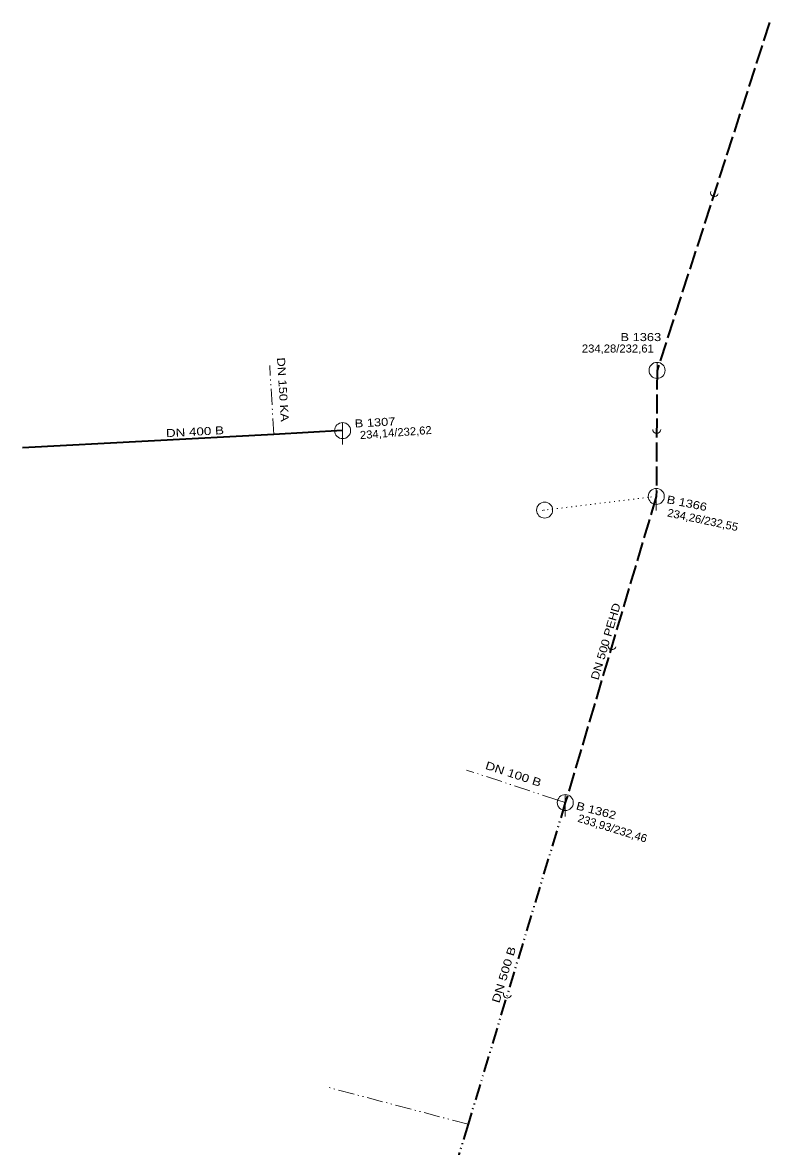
# Model space of a CAD drawing. Extents: x -645297 to -645138, y -1043752 to -1043474.
# Drawn here: x -645265.2 to -645172, y -1043614.2 to -1043473.8 of the extents above; entities that cross this region are included whole.
import ezdxf
from ezdxf.enums import TextEntityAlignment as Align

# ---------------------------------------------------------------- set-up
doc = ezdxf.new("R2010")
doc.units = 0
doc.header["$LTSCALE"] = 0.4
for name, pattern in [('DASH_DOUBLE_DOT', [9.2, 5, -1.2, 0.3, -1.2, 0.3, -1.2]), ('DOTTED', [1.5, 0.3, -1.2]), ('LONG_DASHED', [7.5, 6, -1.5])]:
    doc.linetypes.add(name, pattern=pattern)
for name, color, linetype, lineweight in [('10', 7, 'Continuous', 13), ('14', 7, 'Continuous', 13), ('23', 7, 'LONG_DASHED', 35), ('24', 7, 'DASH_DOUBLE_DOT', 35), ('34', 7, 'DASH_DOUBLE_DOT', 13)]:
    doc.layers.add(name, color=color, linetype=linetype, lineweight=lineweight)
doc.layers.add('29', color=7, linetype='Continuous')
doc.layers.add('39', color=7, linetype='Continuous')

msp = doc.modelspace()

# ---------------------------------------------------------------- linework, layer by layer
at = {"layer": '10'}
for p, q in [((-645186.03, -1043516.29), (-645186.03, -1043519.038)), ((-645225.28, -1043523.82), (-645225.28, -1043526.568)), ((-645186.12, -1043532.03), (-645186.12, -1043534.778)), ((-645197.48, -1043570.27), (-645197.48, -1043573.018))]:
    msp.add_line(p, q, dxfattribs=at)
for centre, radius in [((-645186.0297, -1043517.2903), 1.0002), ((-645225.2797, -1043524.8203), 1.0002), ((-645186.1197, -1043533.0303), 1.0002), ((-645200.0601, -1043534.7401), 1), ((-645197.4797, -1043571.2703), 1.0002)]:
    msp.add_circle(centre, radius, dxfattribs=at)
at = {"layer": '14'}
for centre, start, end in [((-645178.8568, -1043495.0895), 162.09279, 342.09279), ((-645186.0726, -1043524.6604), 179.67239, 359.67239), ((-645191.6581, -1043551.671), 163.45484, 343.45484), ((-645204.7084, -1043595.1896), 163.18642, 343.18642)]:
    msp.add_arc(centre, 0.5, start, end, dxfattribs=at)
at = {"layer": '23'}
for p, q in [((-645171.99, -1043473.84), (-645186.03, -1043517.29)), ((-645186.03, -1043517.29), (-645186.12, -1043533.03)), ((-645186.12, -1043533.03), (-645197.48, -1043571.27))]:
    msp.add_line(p, q, dxfattribs=at)
at = {"layer": '24'}
msp.add_line((-645197.48, -1043571.27), (-645209.622, -1043611.451), dxfattribs=at)
at = {"layer": '24', "linetype": 'Continuous'}
msp.add_lwpolyline([(-645225.28, -1043524.82), (-645233.868, -1043525.283), (-645265.243, -1043526.973)], dxfattribs=at)
at = {"layer": '24'}
msp.add_lwpolyline([(-645209.622, -1043611.451), (-645212.225, -1043620.066), (-645213.814, -1043626.756), (-645215.918, -1043635.618)], dxfattribs=at)
at = {"layer": '34'}
for p, q in [((-645233.868, -1043525.283), (-645234.386, -1043516.699)), ((-645209.622, -1043611.451), (-645227.259, -1043606.789))]:
    msp.add_line(p, q, dxfattribs=at)
at = {"layer": '34', "linetype": 'DOTTED'}
for points in [[(-645186.12, -1043533.03), (-645187.113, -1043533.152), (-645200.06, -1043534.74)], [(-645200.06, -1043534.74), (-645200.23, -1043534.764), (-645200.541, -1043534.798)]]:
    msp.add_lwpolyline(points, dxfattribs=at)
at = {"layer": '34'}
msp.add_lwpolyline([(-645197.48, -1043571.27), (-645198.43, -1043570.958), (-645209.815, -1043567.215)], dxfattribs=at)

# ---------------------------------------------------------------- texts
at = {"layer": '29', "width": 1.2}
msp.add_text('B 1363', height=1, dxfattribs=at).set_placement((-645190.596, -1043513.633))
at = {"layer": '29', "width": 1.05}
msp.add_text('234,28/232,61', height=1, dxfattribs=at).set_placement((-645190.924, -1043515.06), align=Align.CENTER)
at = {"layer": '29', "width": 1.2}
for s, rotation, p in [('B 1307', 3.234, (-645223.745, -1043524.434)), ('B 1366', 348.608, (-645184.889, -1043533.867)), ('B 1362', 345.423, (-645196.206, -1043572.11))]:
    msp.add_text(s, height=1, rotation=rotation, dxfattribs=at).set_placement(p)
at = {"layer": '29'}
for s, rotation, width, p in [('DN 400 B', 3.083, 1.25, (-645243.6879, -1043525.4474)), ('234,14/232,62', 4.2, 1.05, (-645218.6051, -1043525.5502)), ('234,26/232,55', 348.062, 1.05, (-645180.4219, -1043536.4492)), ('DN 500 PEHD', 73.455, 1.15, (-645191.9616, -1043551.2854)), ('233,93/232,46', 342.894, 1.05, (-645191.7391, -1043574.9619)), ('DN 500 B', 73.186, 1.25, (-645204.6723, -1043592.9146))]:
    msp.add_text(s, height=1, rotation=rotation, dxfattribs=dict(at, width=width)).set_placement(p, align=Align.CENTER)
at = {"layer": '39'}
for s, rotation, width, p in [('DN 150 KA', 273.453, 1.2, (-645233.2317, -1043519.7189)), ('DN 100 B', 341.802, 1.25, (-645204.1121, -1043568.1763))]:
    msp.add_text(s, height=1, rotation=rotation, dxfattribs=dict(at, width=width)).set_placement(p, align=Align.CENTER)

doc.saveas('drawing.dxf')
